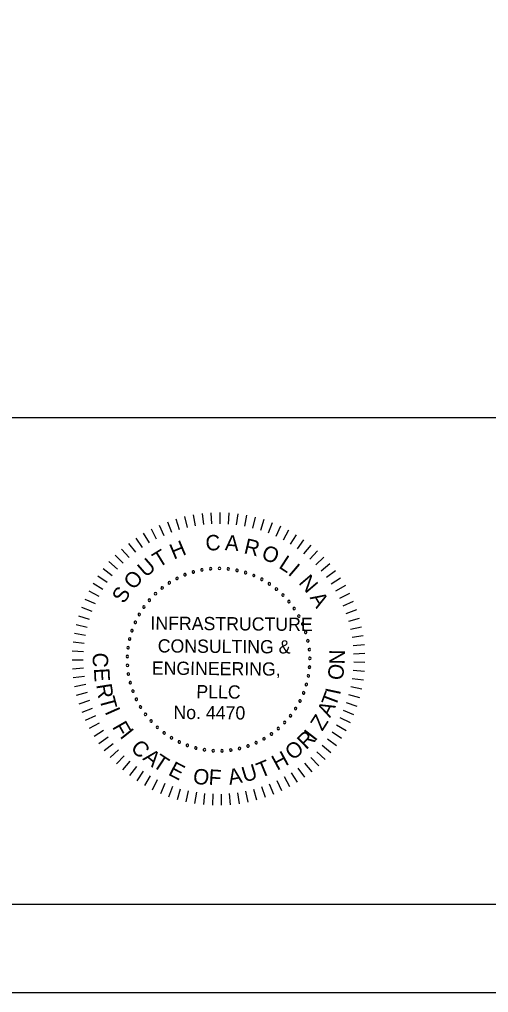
# Model space of a CAD drawing. Extents: x -133.1 to -97, y -1.7 to 20.3.
# Drawn here: x -107.93 to -105.28, y -1.69 to 3.81 of the extents above; entities that cross this region are included whole.
import ezdxf

# ---------------------------------------------------------------- set-up
doc = ezdxf.new("R2010")
doc.units = 0
for name, color, linetype in [('BR_BORDER LINES', 7, 'Continuous'), ('BR_TEXT', 7, 'Continuous'), ('Level 31', 7, 'Continuous')]:
    doc.layers.add(name, color=color, linetype=linetype)

msp = doc.modelspace()

# ---------------------------------------------------------------- linework, layer by layer
at = {"layer": 'BR_BORDER LINES'}
for p, q in [((-110.5071, 1.5591), (-105.1419, 1.5591)), ((-131.3076, -1.191), (-97.6416, -1.191))]:
    msp.add_line(p, q, dxfattribs=at)
at = {"layer": 'BR_TEXT'}
for p, q in [((-107.0007, 0.9998), (-106.9858, 0.9379)), ((-106.9512, 1.01), (-106.9401, 0.9473)), ((-106.9012, 1.0172), (-106.894, 0.9539)), ((-106.8509, 1.0213), (-106.8476, 0.9578)), ((-106.8005, 1.0224), (-106.801, 0.9587)), ((-106.75, 1.0204), (-106.7544, 0.9569)), ((-106.6998, 1.0153), (-106.7081, 0.9522)), ((-106.65, 1.0071), (-106.6621, 0.9446)), ((-106.6007, 0.996), (-106.6166, 0.9343)), ((-107.1439, 0.9513), (-107.1181, 0.8932)), ((-107.0972, 0.9704), (-107.0749, 0.9107)), ((-107.0494, 0.9866), (-107.0308, 0.9257)), ((-106.5523, 0.9818), (-106.5719, 0.9213)), ((-106.5048, 0.9648), (-106.528, 0.9055)), ((-106.4584, 0.9448), (-106.4852, 0.8871)), ((-107.2335, 0.9049), (-107.2008, 0.8503)), ((-107.1895, 0.9295), (-107.1601, 0.873)), ((-106.4133, 0.9221), (-106.4436, 0.8661)), ((-106.3697, 0.8967), (-106.4034, 0.8426)), ((-107.3168, 0.8478), (-107.2776, 0.7976)), ((-107.276, 0.8776), (-107.24, 0.8251)), ((-106.3277, 0.8686), (-106.3646, 0.8167)), ((-106.2875, 0.8381), (-106.3275, 0.7885)), ((-107.3925, 0.7811), (-107.3475, 0.736)), ((-107.3557, 0.8156), (-107.3135, 0.7679)), ((-106.2493, 0.8051), (-106.2922, 0.7581)), ((-107.4272, 0.7444), (-107.3795, 0.7022)), ((-106.2131, 0.7699), (-106.2588, 0.7256)), ((-106.1791, 0.7326), (-106.2275, 0.6911)), ((-107.4895, 0.665), (-107.437, 0.6289)), ((-107.4595, 0.7056), (-107.4094, 0.6664)), ((-106.1475, 0.6932), (-106.1983, 0.6548)), ((-107.5169, 0.6226), (-107.4623, 0.5897)), ((-106.1184, 0.652), (-106.1714, 0.6167)), ((-106.0918, 0.6091), (-106.1469, 0.5771)), ((-107.5416, 0.5786), (-107.4852, 0.5491)), ((-106.0679, 0.5646), (-106.1248, 0.5361)), ((-107.5637, 0.5332), (-107.5055, 0.5072)), ((-106.0467, 0.5188), (-106.1052, 0.4938)), ((-107.5829, 0.4865), (-107.5233, 0.4641)), ((-106.0283, 0.4718), (-106.0883, 0.4504)), ((-107.6126, 0.3901), (-107.5507, 0.3751)), ((-107.5992, 0.4387), (-107.5384, 0.42)), ((-106.0129, 0.4237), (-106.0741, 0.406)), ((-107.623, 0.3407), (-107.5604, 0.3295)), ((-106.0004, 0.3748), (-106.0625, 0.3608)), ((-107.6304, 0.2907), (-107.5672, 0.2834)), ((-105.9909, 0.3252), (-106.0538, 0.3151)), ((-105.9845, 0.2751), (-106.0479, 0.2689)), ((-107.6348, 0.2404), (-107.5712, 0.237)), ((-105.9811, 0.2247), (-106.0448, 0.2224)), ((-107.636, 0.19), (-107.5723, 0.1904)), ((-105.9809, 0.1743), (-106.0445, 0.1758)), ((-107.6342, 0.1395), (-107.5706, 0.1438)), ((-105.9836, 0.1239), (-106.0471, 0.1292)), ((-107.6293, 0.0893), (-107.5661, 0.0974)), ((-105.9895, 0.0737), (-106.0525, 0.0829)), ((-107.6213, 0.0394), (-107.5588, 0.0514)), ((-107.6103, -0.0099), (-107.5487, 0.0059)), ((-105.9984, 0.024), (-106.0607, 0.0371)), ((-107.5964, -0.0584), (-107.5358, -0.0388)), ((-106.0252, -0.0733), (-106.0855, -0.0527)), ((-106.0103, -0.025), (-106.0717, -0.0082)), ((-107.5795, -0.106), (-107.5202, -0.0828)), ((-106.043, -0.1205), (-106.1019, -0.0963)), ((-107.5597, -0.1524), (-107.5019, -0.1256)), ((-106.0636, -0.1666), (-106.1209, -0.1389)), ((-107.5371, -0.1976), (-107.4811, -0.1673)), ((-107.5119, -0.2413), (-107.4578, -0.2077)), ((-106.087, -0.2113), (-106.1426, -0.1802)), ((-107.484, -0.2834), (-107.4321, -0.2465)), ((-106.1418, -0.2961), (-106.1931, -0.2584)), ((-106.1131, -0.2545), (-106.1667, -0.22)), ((-107.4536, -0.3237), (-107.404, -0.2837)), ((-107.4208, -0.362), (-107.3737, -0.3191)), ((-106.2065, -0.3735), (-106.2529, -0.3299)), ((-106.173, -0.3358), (-106.2219, -0.2951)), ((-107.3857, -0.3983), (-107.3413, -0.3527)), ((-107.3485, -0.4324), (-107.307, -0.3841)), ((-106.2423, -0.4092), (-106.2859, -0.3628)), ((-107.3092, -0.4642), (-107.2708, -0.4135)), ((-106.32, -0.4736), (-106.3576, -0.4222)), ((-106.2801, -0.4426), (-106.3208, -0.3936)), ((-107.2681, -0.4935), (-107.2328, -0.4405)), ((-107.2253, -0.5203), (-107.1933, -0.4652)), ((-107.1809, -0.5444), (-107.1523, -0.4875)), ((-106.4498, -0.5513), (-106.4774, -0.4939)), ((-106.4049, -0.528), (-106.436, -0.4725)), ((-106.3616, -0.5021), (-106.3961, -0.4485)), ((-107.1352, -0.5657), (-107.1101, -0.5072)), ((-107.0882, -0.5842), (-107.0668, -0.5243)), ((-107.0402, -0.5998), (-107.0225, -0.5387)), ((-106.5915, -0.6041), (-106.6083, -0.5427)), ((-106.5432, -0.5894), (-106.5637, -0.5291)), ((-106.4959, -0.5718), (-106.52, -0.5128)), ((-106.9913, -0.6125), (-106.9773, -0.5504)), ((-106.9418, -0.6221), (-106.9316, -0.5593)), ((-106.8918, -0.6288), (-106.8854, -0.5654)), ((-106.8414, -0.6323), (-106.8389, -0.5687)), ((-106.7909, -0.6328), (-106.7923, -0.5691)), ((-106.7405, -0.6302), (-106.7458, -0.5667)), ((-106.6903, -0.6245), (-106.6995, -0.5615)), ((-106.6406, -0.6158), (-106.6536, -0.5535))]:
    msp.add_line(p, q, dxfattribs=at)
for centre, start, end in [((-106.9977, 0.6702), 21.6807, 201.6807), ((-106.9977, 0.6702), 201.6807, 21.6807), ((-106.9506, 0.6862), 16.1422, 196.1422), ((-106.9506, 0.6862), 196.1422, 16.1422), ((-106.9021, 0.6977), 10.6038, 190.6038), ((-106.9021, 0.6977), 190.6038, 10.6038), ((-106.8527, 0.7043), 5.0653, 185.0653), ((-106.8527, 0.7043), 185.0653, 5.0653), ((-106.8029, 0.7062), 359.5268, 179.5268), ((-106.8029, 0.7062), 179.5268, 359.5268), ((-106.7531, 0.7033), 173.9884, 353.9884), ((-106.7531, 0.7033), 353.9884, 173.9884), ((-106.7039, 0.6956), 168.4499, 348.4499), ((-106.7039, 0.6956), 348.4499, 168.4499), ((-106.6557, 0.6832), 162.9114, 342.9114), ((-106.6557, 0.6832), 342.9114, 162.9114), ((-106.6088, 0.6662), 157.373, 337.373), ((-106.6088, 0.6662), 337.373, 157.373), ((-107.0864, 0.6248), 32.7576, 212.7576), ((-107.0864, 0.6248), 212.7576, 32.7576), ((-107.0431, 0.6496), 27.2191, 207.2191), ((-107.0431, 0.6496), 207.2191, 27.2191), ((-106.5639, 0.6447), 151.8345, 331.8345), ((-106.5639, 0.6447), 331.8345, 151.8345), ((-106.5212, 0.619), 146.2961, 326.2961), ((-106.5212, 0.619), 326.2961, 146.2961), ((-107.1646, 0.5633), 43.8345, 223.8345), ((-107.1646, 0.5633), 223.8345, 43.8345), ((-107.127, 0.5959), 38.2961, 218.2961), ((-107.127, 0.5959), 218.2961, 38.2961), ((-106.4811, 0.5893), 140.7576, 320.7576), ((-106.4811, 0.5893), 320.7576, 140.7576), ((-106.4442, 0.5559), 135.2191, 315.2191), ((-106.4442, 0.5559), 315.2191, 135.2191), ((-107.1989, 0.5271), 49.373, 229.373), ((-107.1989, 0.5271), 229.373, 49.373), ((-106.4106, 0.5191), 129.6807, 309.6807), ((-106.4106, 0.5191), 309.6807, 129.6807), ((-107.2563, 0.4458), 60.4499, 240.4499), ((-107.2563, 0.4458), 240.4499, 60.4499), ((-107.2296, 0.4879), 54.9114, 234.9114), ((-107.2296, 0.4879), 234.9114, 54.9114), ((-106.3808, 0.4792), 124.1422, 304.1422), ((-106.3808, 0.4792), 304.1422, 124.1422), ((-106.3549, 0.4366), 118.6038, 298.6038), ((-106.3549, 0.4366), 298.6038, 118.6038), ((-107.2788, 0.4014), 65.9884, 245.9884), ((-107.2788, 0.4014), 245.9884, 65.9884), ((-106.3333, 0.3917), 113.0653, 293.0653), ((-106.3333, 0.3917), 293.0653, 113.0653), ((-107.297, 0.3549), 71.5268, 251.5268), ((-107.297, 0.3549), 251.5268, 71.5268), ((-106.3161, 0.3449), 107.5268, 287.5268), ((-106.3161, 0.3449), 287.5268, 107.5268), ((-107.3106, 0.307), 77.0653, 257.0653), ((-107.3106, 0.307), 257.0653, 77.0653), ((-106.3035, 0.2967), 101.9884, 281.9884), ((-106.3035, 0.2967), 281.9884, 101.9884), ((-107.3195, 0.258), 82.6038, 262.6038), ((-107.3195, 0.258), 262.6038, 82.6038), ((-106.2956, 0.2475), 96.4499, 276.4499), ((-106.2956, 0.2475), 276.4499, 96.4499), ((-107.3236, 0.2083), 88.1422, 268.1422), ((-107.3229, 0.1585), 93.6807, 273.6807), ((-107.3236, 0.2083), 268.1422, 88.1422), ((-107.3229, 0.1585), 273.6807, 93.6807), ((-106.2925, 0.1977), 90.9114, 270.9114), ((-106.2925, 0.1977), 270.9114, 90.9114), ((-107.3174, 0.109), 99.2191, 279.2191), ((-107.3174, 0.109), 279.2191, 99.2191), ((-106.2942, 0.1479), 85.373, 265.373), ((-106.2942, 0.1479), 265.373, 85.373), ((-107.3071, 0.0602), 104.7576, 284.7576), ((-107.3071, 0.0602), 284.7576, 104.7576), ((-106.312, 0.05), 74.2961, 254.2961), ((-106.312, 0.05), 254.2961, 74.2961), ((-106.3007, 0.0985), 79.8345, 259.8345), ((-106.3007, 0.0985), 259.8345, 79.8345), ((-107.2922, 0.0126), 110.2961, 290.2961), ((-107.2922, 0.0126), 290.2961, 110.2961), ((-106.3279, 0.0028), 68.7576, 248.7576), ((-106.3279, 0.0028), 248.7576, 68.7576), ((-107.2728, -0.0332), 115.8345, 295.8345), ((-107.2728, -0.0332), 295.8345, 115.8345), ((-106.3483, -0.0427), 63.2191, 243.2191), ((-106.3483, -0.0427), 243.2191, 63.2191), ((-107.249, -0.077), 121.373, 301.373), ((-107.249, -0.077), 301.373, 121.373), ((-106.3729, -0.086), 57.6807, 237.6807), ((-106.3729, -0.086), 237.6807, 57.6807), ((-107.2211, -0.1183), 126.9114, 306.9114), ((-107.2211, -0.1183), 306.9114, 126.9114), ((-107.1894, -0.1567), 132.4499, 312.4499), ((-107.1894, -0.1567), 312.4499, 132.4499), ((-106.4342, -0.1645), 46.6038, 226.6038), ((-106.4342, -0.1645), 226.6038, 46.6038), ((-106.4016, -0.1267), 52.1422, 232.1422), ((-106.4016, -0.1267), 232.1422, 52.1422), ((-107.1541, -0.1919), 137.9884, 317.9884), ((-107.1541, -0.1919), 317.9884, 137.9884), ((-107.1156, -0.2235), 143.5268, 323.5268), ((-107.1156, -0.2235), 323.5268, 143.5268), ((-106.4702, -0.1989), 41.0653, 221.0653), ((-106.4702, -0.1989), 221.0653, 41.0653), ((-107.0742, -0.2512), 149.0653, 329.0653), ((-107.0742, -0.2512), 329.0653, 149.0653), ((-107.0303, -0.2749), 154.6038, 334.6038), ((-107.0303, -0.2749), 334.6038, 154.6038), ((-106.5957, -0.2793), 24.4499, 204.4499), ((-106.5513, -0.2566), 29.9884, 209.9884), ((-106.5513, -0.2566), 209.9884, 29.9884), ((-106.5093, -0.2297), 35.5268, 215.5268), ((-106.5093, -0.2297), 215.5268, 35.5268), ((-106.9843, -0.2941), 160.1422, 340.1422), ((-106.9843, -0.2941), 340.1422, 160.1422), ((-106.9367, -0.3089), 165.6807, 345.6807), ((-106.9367, -0.3089), 345.6807, 165.6807), ((-106.8879, -0.3189), 171.2191, 351.2191), ((-106.8879, -0.3189), 351.2191, 171.2191), ((-106.8384, -0.3242), 356.7576, 176.7576), ((-106.8384, -0.3242), 176.7576, 356.7576), ((-106.7885, -0.3248), 2.2961, 182.2961), ((-106.7885, -0.3248), 182.2961, 2.2961), ((-106.7389, -0.3205), 7.8345, 187.8345), ((-106.7389, -0.3205), 187.8345, 7.8345), ((-106.6899, -0.3114), 13.373, 193.373), ((-106.6899, -0.3114), 193.373, 13.373), ((-106.642, -0.2976), 18.9114, 198.9114), ((-106.642, -0.2976), 198.9114, 18.9114), ((-106.5957, -0.2793), 204.4499, 24.4499)]:
    msp.add_arc(centre, 0.00701, start, end, dxfattribs=at)
at = {"layer": 'Level 31'}
msp.add_lwpolyline([(-133.1409, -1.691), (-97.141, -1.691), (-97.141, 20.309), (-133.1409, 20.309)], close=True, dxfattribs=at)

# ---------------------------------------------------------------- texts
at = {"layer": 'BR_TEXT'}
for s, height, rotation, p in [('C', 0.0872, 4.7281, (-106.8784, 0.8048)), ('A', 0.0872, 355.6981, (-106.7739, 0.8098)), ('H', 0.0872, 22.7882, (-107.0612, 0.7554)), ('R', 0.0872, 346.6681, (-106.6696, 0.7928)), ('O', 0.0872, 337.638, (-106.5719, 0.763)), ('T', 0.0872, 31.8182, (-107.1461, 0.7078)), ('L', 0.0872, 327.108, (-106.4731, 0.7125)), ('U', 0.0872, 40.8482, (-107.2194, 0.6516)), ('I', 0.0872, 319.578, (-106.4205, 0.6747)), ('O', 0.0872, 49.8782, (-107.2864, 0.5806)), ('N', 0.0872, 310.548, (-106.3597, 0.6239)), ('S', 0.0872, 58.9083, (-107.3418, 0.5024)), ('A', 0.0872, 301.5179, (-106.2946, 0.5415)), ('INFRASTRUCTURE', 0.074771, 359.5268, (-107.1932, 0.3599)), ('CONSULTING &', 0.074771, 359.5268, (-107.1519, 0.2313)), ('C', 0.0872, 267.025, (-107.5168, 0.2325)), ('N', 0.0872, 89.2085, (-106.0953, 0.1628)), ('ENGINEERING,', 0.074771, 359.5268, (-107.1855, 0.1059)), ('E', 0.0872, 273.025, (-107.5124, 0.1409)), ('O', 0.0872, 83.2085, (-106.1064, 0.0713)), ('R', 0.0872, 279.025, (-107.4996, 0.0487)), ('PLLC', 0.07477, 359.5268, (-106.9338, -0.0277)), ('T', 0.0872, 69.3954, (-106.1476, -0.0805)), ('I', 0.0872, 77.9093, (-106.1219, -0.013)), ('T', 0.0872, 285.025, (-107.4822, -0.0301)), ('I', 0.0872, 293.7713, (-107.4525, -0.1032)), ('No. 4470', 0.07477, 359.5268, (-107.0633, -0.1446)), ('A', 0.0872, 63.3954, (-106.1784, -0.1408)), ('F', 0.0872, 299.7713, (-107.4113, -0.1893)), ('Z', 0.0872, 57.3954, (-106.2222, -0.2172)), ('I', 0.0872, 308.5268, (-107.3692, -0.2431)), ('R', 0.0872, 44.5268, (-106.3127, -0.3221)), ('I', 0.0872, 52.3339, (-106.2633, -0.2748)), ('C', 0.0872, 314.5268, (-107.3099, -0.3133)), ('O', 0.0872, 38.5268, (-106.3893, -0.3821)), ('A', 0.0872, 320.5268, (-107.2407, -0.3718)), ('H', 0.0872, 28.5268, (-106.4774, -0.4381)), ('T', 0.0872, 326.5268, (-107.1863, -0.4103)), ('T', 0.0872, 22.5268, (-106.5706, -0.4799)), ('E', 0.0872, 332.5268, (-107.0977, -0.4581)), ('O', 0.0872, 350.5268, (-106.9576, -0.507)), ('F', 0.0872, 356.5268, (-106.8661, -0.5161)), ('A', 0.0872, 10.5268, (-106.7462, -0.5177)), ('U', 0.0872, 16.5268, (-106.6623, -0.5042))]:
    msp.add_text(s, height=height, rotation=rotation, dxfattribs=at).set_placement(p)

doc.saveas('drawing.dxf')
